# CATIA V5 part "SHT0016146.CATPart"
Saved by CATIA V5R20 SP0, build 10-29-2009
Part number: SHT0016146
Bounding box of the stored display mesh (mm): x -141.9 to 25.758, y -864.5 to -593.501, z 15.9 to 106.4
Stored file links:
  E:\宋国明\项目\02-福田A6-张甲\骨架钣金\2D\宽车主驾底支架\SHT0016146-宽车主驾驶后侧钣金\SHT0016146.CATPart

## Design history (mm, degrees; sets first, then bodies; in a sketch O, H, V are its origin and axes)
Body1 (main body)
Body2 "SHT0016146-宽车主驾驶后侧钣金"
  Solid1: solid without history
